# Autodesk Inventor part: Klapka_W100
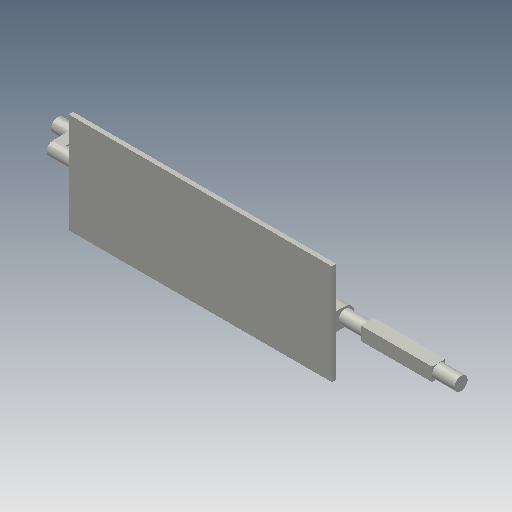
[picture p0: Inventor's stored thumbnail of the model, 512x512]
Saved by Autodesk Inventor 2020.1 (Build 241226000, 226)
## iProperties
Created: 2005-10
Part Number: Klapka_W100
Document SubType Name: Modeling
Designer: F.Stasiak
Density: 1 g/cm^3
Material: Ogólny
Appearance: Gładkie — w kolorze kości słoniowej
Manager: www.cadconsulting.pl
Company: Fabian Stasiak CAD Consulting
Author: F.Stasiak
Subject: Zbiór ćwiczeń. Autodesk Inventor 2020. Kurs podstawowy
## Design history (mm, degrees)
sketch "Szkic1"
  geometry: L1 (-59, 0)-(59, 0); L2 (59, 0)-(59, -45); L3 (59, -45)-(-59, -45); L4 (-59, -45)-(-59, 0); 2 further points
  constraints: 8 end point, 2 parallel, 1 coincident, 1 horizontal, 1 midpoint, 1 perpendicular
  dimensions: "d0" = 45 distance of L3.end L1.start; "d1" = 118 distance of L2.end L3.end
extrude "Wyciągnięcie proste1" new body sketch "Szkic1" distance "d2" = 2; taper "d3" = 0 deg
sketch "Szkic2"
  geometry: L1 (0, 45)-(0, 0) reference; L2 (0, 26.5)-(0, 18.5); L3 (0, 18.5)-(4, 18.5); L4 (4, 26.5)-(0, 26.5); A1 r 4 centre (4, 22.5) between (4, 18.5) and (4, 26.5); 1 further point
  constraints: 6 end point, 2 midpoint, 2 point on circle, 2 tangent, 1 centre point, 1 collinear, 1 parallel, 1 perpendicular
  dimensions: "d4" = 4 radius of A1; "d5" = 4 distance of L2.end L3.end (= d4)
extrude "Wyciągnięcie proste2" join sketch "Szkic2" distance "d6" = 5; taper "d7" = 0 deg
sketch "Szkic3"
  geometry: C1 r 3 at (6, 22.5); A1 r 4 centre (6, 22.5) between (6, 18.5) and (6, 26.5) reference
  constraints: 1 centre point, 1 coincident
  dimensions: "d8" = 6 diameter of C1
extrude "Wyciągnięcie proste3" join sketch "Szkic3" distance "d9" = 10; taper "d10" = 0 deg
mirror "Lustro1"
sketch "Szkic4"
  geometry: L1 (3, -3)-(-3, -3); L2 (-3, -3)-(-3, 3); L3 (-3, 3)-(3, 3); L4 (3, 3)-(3, -3); 3 further points
  constraints: 8 end point, 1 coincident, 1 horizontal alignment, 1 midpoint, 8 other
extrude "Wyciągnięcie proste4" join sketch "Szkic4" distance "d11" = 32; taper "d12" = 0 deg
sketch "Szkic5"
  geometry: L1 (-3, -3)-(-3, 3) reference; L2 (3, -3)-(-3, -3) reference; L3 (3, 3)-(3, -3) reference; L4 (-3, 3)-(3, 3) reference; C1 r 3 at (0, 0)
  constraints: 1 centre point
extrude "Wyciągnięcie proste5" join sketch "Szkic5" distance "d13" = 10; taper "d14" = 0 deg
node "Płaszczyzna konstrukcyjna1"
sketch "Szkic6"
  geometry: C1 r 3 at (0, 0) reference
extrude "Wyciągnięcie proste6" join sketch "Szkic6" distance "d15" = 3; taper "d16" = 0 deg
sketch "Szkic7"
  geometry: L1 (-10, 3)-(0, 3); L2 (-10, -3)-(0, -3); C1 r 3 at (0, 0) reference; A1 r 3 centre (0, 0) between (0, 3) and (0, -3) reference; A2 r 3 centre (-10, 0) between (-10, 3) and (-10, -3)
  constraints: 4 end point, 4 point on circle, 4 tangent, 1 centre point, 1 equal radius, 1 horizontal
  dimensions: "d17" = 10 distance of A1.centre A2.centre
extrude "Wyciągnięcie proste7" join sketch "Szkic7" distance "d18" = 5; taper "d19" = 0 deg
sketch "Szkic8"
  geometry: C1 r 3 at (-10, 0); A1 r 3 centre (-10, 0) between (-10, 3) and (-10, -3) reference
  constraints: 1 centre point, 1 coincident, 1 concentric
extrude "Wyciągnięcie proste8" join sketch "Szkic8" distance "d20" = 8; taper "d21" = 0 deg
node "Płaszczyzna konstrukcyjna2"
node "Bryła1"
node "Korpusy bryłowe"
node "Korpusy powierzchniowe"
node "Pętla rzutowana1"
node "Pętla rzutowana2"
node "Pętla rzutowana3"
